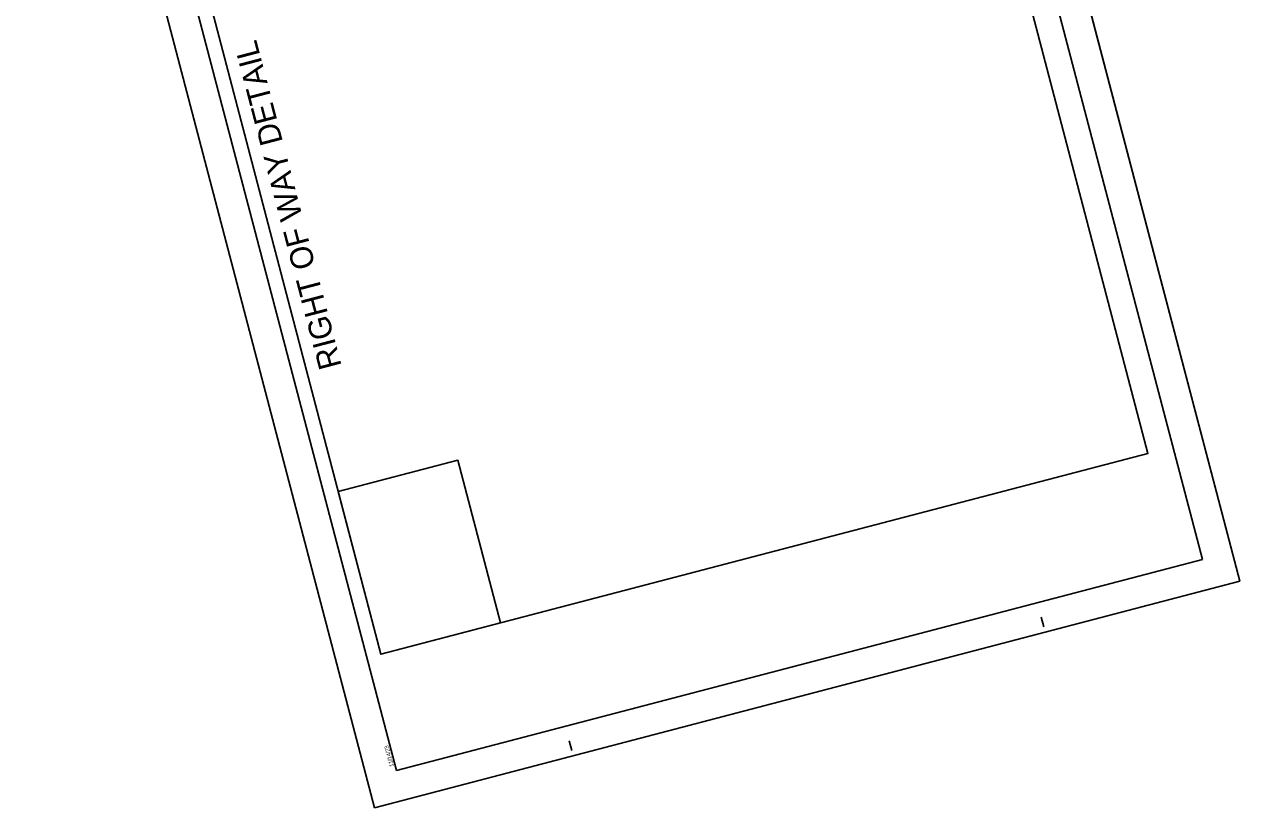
# Model space of a CAD drawing. Extents: x 1366699 to 1368206, y 878140 to 880064.
# Drawn here: x 1366711 to 1368206, y 878140 to 879105 of the extents above; entities that cross this region are included whole.
import ezdxf

# ---------------------------------------------------------------- set-up
doc = ezdxf.new("R2010")
doc.units = 0
for name, color, linetype in [('Level 20', 7, 'Continuous'), ('Prop Shade Medium', 7, 'Continuous'), ('Sheet Plan CELL', 7, 'Continuous'), ('Sheet_Plot_Border_Outside_CELL', 7, 'Continuous'), ('Sheet_Title_Block_Text', 7, 'Continuous'), ('Typical Terminator CELL', 7, 'Continuous')]:
    doc.layers.add(name, color=color, linetype=linetype)

msp = doc.modelspace()

# ---------------------------------------------------------------- linework, layer by layer
at = {"layer": 'Prop Shade Medium'}
for p, q in [((1368160.1, 878446.1), (1367748.1, 880018)), ((1366756.6, 879758.2), (1367168.6, 878186.2)), ((1368160.1, 878446.1), (1367168.6, 878186.2)), ((1367964.8, 878362.9), (1367961.6, 878375)), ((1367384.4, 878210.8), (1367381.2, 878222.9)), ((1367153.7, 878213.3), (1367153.7, 878213.3))]:
    msp.add_line(p, q, dxfattribs=at)
at = {"layer": 'Sheet Plan CELL'}
msp.add_line((1368205.9, 878419.3), (1368205.9, 878419.3), dxfattribs=at)
at = {"layer": 'Sheet_Plot_Border_Outside_CELL'}
for points in [[(1366870, 879396.1), (1367149.6, 878329.3), (1367149.6, 878329.3), (1368092.9, 878576.5), (1368092.9, 878576.5), (1367795.9, 879709.6)], [(1367149.6, 878329.3), (1367097.1, 878529.5), (1367244.1, 878568.1), (1367296.6, 878367.8)]]:
    msp.add_lwpolyline(points, close=True, dxfattribs=at)
at = {"layer": 'Sheet_Title_Block_Text'}
for p, q in [((1368205.9, 878419.3), (1367774.9, 880063.8)), ((1367141.8, 878140.5), (1366710.8, 879784.9)), ((1368205.9, 878419.3), (1367141.8, 878140.5))]:
    msp.add_line(p, q, dxfattribs=at)
at = {"layer": 'Typical Terminator CELL'}
msp.add_lwpolyline([(1367141.8, 878140.5), (1366710.8, 879784.9), (1367774.9, 880063.8), (1368205.9, 878419.3)], close=True, dxfattribs=at)

# ---------------------------------------------------------------- texts
at = {"layer": 'Level 20'}
msp.add_text('RIGHT OF WAY DETAIL', height=28, rotation=104.6851, dxfattribs=at).set_placement((1367101.4, 878684.1))
at = {"layer": 'Prop Shade Medium'}
msp.add_text('11/14/23', height=5, rotation=104.6851, dxfattribs=at).set_placement((1367165.3, 878191.5))

doc.saveas('drawing.dxf')
